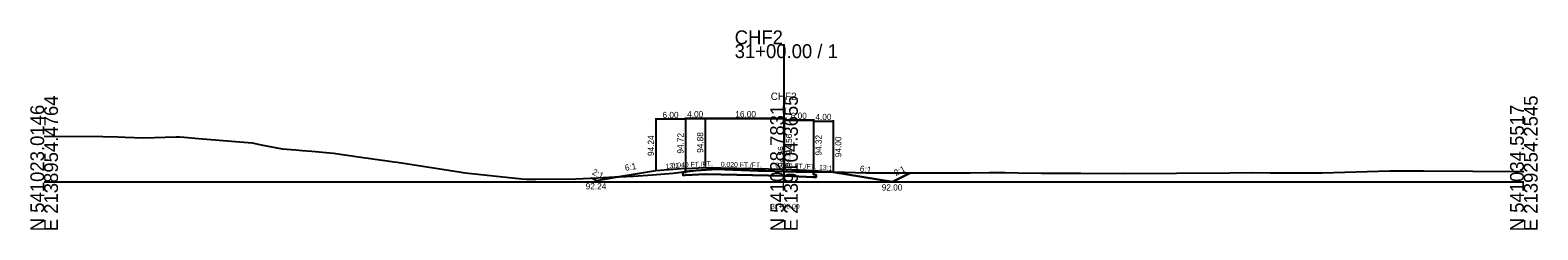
# Model space of a CAD drawing. Extents: x -12831 to 2303, y -10 to 39065.
# Drawn here: x 997.2 to 1302.8, y 1990.3 to 2030.7 of the extents above; entities that cross this region are included whole.
import ezdxf

# ---------------------------------------------------------------- set-up
doc = ezdxf.new("R2010")
doc.units = 0
for name, color, linetype in [('Level 5', 7, 'Continuous'), ('Level 53', 7, 'Continuous'), ('Level 54', 7, 'Continuous'), ('Level 55', 7, 'Continuous'), ('Level 7', 7, 'Continuous'), ('RD_GPK_XS_Cell', 7, 'Continuous'), ('RD_XS_EwShp', 7, 'Continuous'), ('RD_XS_ExGround', 7, 'Continuous'), ('RD_XS_Pave', 7, 'Continuous'), ('RD_XS_TX_Baseline', 7, 'Continuous'), ('RD_XS_TX_Ditch', 7, 'Continuous'), ('RD_XS_TX_Elev_EX', 7, 'Continuous'), ('RD_XS_TX_Elev_PR', 7, 'Continuous'), ('RD_XS_TX_Station', 7, 'Continuous')]:
    doc.layers.add(name, color=color, linetype=linetype)

msp = doc.modelspace()

# ---------------------------------------------------------------- linework, layer by layer
at = {"layer": 'Level 5'}
for p, q in [((1130, 2002.72), (1130, 2001.88)), ((1156, 2002.32), (1156, 2001.48)), ((1130, 2001.88), (1129.5, 2001.86)), ((1129.5, 2001.86), (1129.5, 2001.36)), ((1129.5, 2001.36), (1130, 2001.38)), ((1134, 2001.54), (1130, 2001.38)), ((1134, 2001.54), (1130, 2001.38)), ((1130, 2001.38), (1134, 2001.54)), ((1150, 2001.22), (1134, 2001.54)), ((1150, 2001.22), (1134, 2001.54)), ((1134, 2001.54), (1150, 2001.22)), ((1134, 2001.54), (1150, 2001.22)), ((1156, 2000.98), (1150, 2001.22)), ((1150, 2001.22), (1156, 2000.98)), ((1150, 2001.22), (1156, 2000.98)), ((1156, 2001.48), (1156.5, 2001.46)), ((1156.5, 2000.96), (1156, 2000.98)), ((1156.5, 2001.46), (1156.5, 2000.96))]:
    msp.add_line(p, q, dxfattribs=at)
at = {"layer": 'Level 54'}
for p, q in [((1124, 2012.87), (1124, 2002.44)), ((1130, 2012.67), (1124, 2012.67)), ((1130, 2013.03), (1130, 2002.92)), ((1130, 2013.03), (1130, 2002.92)), ((1130, 2013.03), (1130, 2002.92)), ((1130, 2012.87), (1130, 2002.92)), ((1130, 2012.83), (1134, 2012.83)), ((1130, 2012.83), (1134, 2012.83)), ((1134, 2012.83), (1130, 2012.83)), ((1134, 2013.03), (1134, 2003.08)), ((1134, 2013.03), (1134, 2003.08)), ((1134, 2013.03), (1134, 2003.08)), ((1134, 2013.03), (1134, 2003.08)), ((1134, 2013.03), (1134, 2003.08)), ((1134, 2013.03), (1134, 2003.08)), ((1134, 2013.03), (1134, 2003.08)), ((1134, 2012.83), (1150, 2012.83)), ((1134, 2012.83), (1150, 2012.83)), ((1150, 2012.83), (1134, 2012.83)), ((1150, 2012.83), (1134, 2012.83)), ((1150, 2013.03), (1150, 2002.76)), ((1150, 2013.03), (1150, 2002.76)), ((1150, 2013.03), (1150, 2002.76)), ((1150, 2013.03), (1150, 2002.76)), ((1150, 2012.71), (1150, 2002.76)), ((1150, 2012.71), (1150, 2002.76)), ((1150, 2012.71), (1150, 2002.76)), ((1150, 2012.51), (1156, 2012.51)), ((1156, 2012.51), (1150, 2012.51)), ((1156, 2012.51), (1150, 2012.51)), ((1156, 2012.71), (1156, 2002.52)), ((1156, 2012.71), (1156, 2002.52)), ((1156, 2012.71), (1156, 2002.52)), ((1156, 2012.47), (1156, 2002.52)), ((1156, 2012.27), (1160, 2012.27)), ((1160, 2012.47), (1160, 2002.2))]:
    msp.add_line(p, q, dxfattribs=at)
at = {"layer": 'Level 7'}
for p, q in [((1124, 2002.24), (1112, 2000.24)), ((1130, 2002.72), (1124, 2002.24)), ((1156, 2002.32), (1160, 2002)), ((1112, 2000.24), (1110.94, 2000.77)), ((1160, 2002), (1172, 2000)), ((1172, 2000), (1175.67, 2001.83))]:
    msp.add_line(p, q, dxfattribs=at)
at = {"layer": 'RD_GPK_XS_Cell'}
for p, q in [((1150, 2000), (1150, 2027.85)), ((1000, 2000), (1150, 2000)), ((1150, 2000), (1300, 2000))]:
    msp.add_line(p, q, dxfattribs=at)
at = {"layer": 'RD_XS_EwShp'}
for points in [[(1116.94, 2001.06), (1119.46, 2001.18), (1123.36, 2001.42), (1127.52, 2001.79), (1130, 2002.08), (1130, 2002.72), (1124, 2002.24)], [(1130, 2002.08), (1130, 2001.88), (1129.5, 2001.86), (1129.5, 2001.36), (1130, 2001.38), (1134, 2001.54), (1150, 2001.22), (1156, 2000.98), (1156.5, 2000.96), (1156.5, 2001.46), (1156, 2001.48), (1156, 2002.04), (1152.47, 2002.04), (1150, 2002.11), (1146.28, 2002.22), (1144.76, 2002.27), (1136.3, 2002.59), (1132.2, 2002.33)], [(1156, 2002.32), (1159.42, 2002.04), (1156, 2002.04)], [(1110.94, 2000.77), (1116.94, 2001.06), (1112, 2000.24)], [(1159.42, 2002.04), (1160.14, 2002.04), (1166.68, 2001.82), (1175.67, 2001.83), (1172, 2000), (1160, 2002)]]:
    msp.add_lwpolyline(points, close=True, dxfattribs=at)
at = {"layer": 'RD_XS_ExGround'}
for p, q in [((1000, 2009.28), (1011.87, 2009.17)), ((1011.87, 2009.17), (1014.96, 2009.14)), ((1014.96, 2009.14), (1016.44, 2009.06)), ((1016.44, 2009.06), (1020.16, 2008.93)), ((1020.16, 2008.93), (1026.77, 2009.11)), ((1026.77, 2009.11), (1027.47, 2009.13)), ((1027.47, 2009.13), (1028.41, 2009.06)), ((1028.41, 2009.06), (1031.26, 2008.81)), ((1031.26, 2008.81), (1042.14, 2007.87)), ((1042.14, 2007.87), (1043.97, 2007.5)), ((1043.97, 2007.5), (1048.27, 2006.67)), ((1048.27, 2006.67), (1051.02, 2006.47)), ((1051.02, 2006.47), (1052.29, 2006.34)), ((1052.29, 2006.34), (1054.3, 2006.21)), ((1054.3, 2006.21), (1058.64, 2005.8)), ((1058.64, 2005.8), (1063.75, 2005.05)), ((1063.75, 2005.05), (1070.04, 2004.18)), ((1070.04, 2004.18), (1070.89, 2004.07)), ((1070.89, 2004.07), (1071.58, 2003.96)), ((1071.58, 2003.96), (1079.8, 2002.68)), ((1079.8, 2002.68), (1084.53, 2001.95)), ((1127.52, 2001.79), (1132.2, 2002.33)), ((1132.2, 2002.33), (1136.3, 2002.59)), ((1136.3, 2002.59), (1144.76, 2002.27)), ((1144.76, 2002.27), (1146.28, 2002.22)), ((1146.28, 2002.22), (1150, 2002.11)), ((1259.1, 2001.85), (1272.81, 2002.26)), ((1272.81, 2002.26), (1273.54, 2002.26)), ((1273.54, 2002.26), (1274.11, 2002.26)), ((1274.11, 2002.26), (1279.65, 2002.24)), ((1279.65, 2002.24), (1299.67, 2002.11)), ((1084.53, 2001.95), (1085.39, 2001.83)), ((1085.39, 2001.83), (1096.85, 2000.6)), ((1096.85, 2000.6), (1097.77, 2000.53)), ((1097.77, 2000.53), (1099.68, 2000.53)), ((1099.68, 2000.53), (1107.79, 2000.61)), ((1107.79, 2000.61), (1119.46, 2001.18)), ((1119.46, 2001.18), (1123.36, 2001.42)), ((1123.36, 2001.42), (1127.52, 2001.79)), ((1150, 2002.11), (1152.47, 2002.04)), ((1152.47, 2002.04), (1160.14, 2002.04)), ((1160.14, 2002.04), (1166.68, 2001.82)), ((1166.68, 2001.82), (1187.75, 2001.84)), ((1187.75, 2001.84), (1191.67, 2001.9)), ((1191.67, 2001.9), (1194.87, 2001.91)), ((1194.87, 2001.91), (1197.41, 2001.85)), ((1197.41, 2001.85), (1202.2, 2001.77)), ((1202.2, 2001.77), (1208.81, 2001.77)), ((1208.81, 2001.77), (1209.82, 2001.78)), ((1209.82, 2001.78), (1210.19, 2001.78)), ((1210.19, 2001.78), (1218.8, 2001.72)), ((1218.8, 2001.72), (1240.34, 2001.81)), ((1240.34, 2001.81), (1245.02, 2001.88)), ((1245.02, 2001.88), (1248.54, 2001.81)), ((1248.54, 2001.81), (1256.68, 2001.8)), ((1256.68, 2001.8), (1259.1, 2001.85)), ((1299.67, 2002.11), (1300, 2002.11))]:
    msp.add_line(p, q, dxfattribs=at)
at = {"layer": 'RD_XS_Pave'}
for p, q in [((1130, 2002.72), (1134, 2002.88)), ((1134, 2002.88), (1150, 2002.56)), ((1150, 2002.56), (1156, 2002.32))]:
    msp.add_line(p, q, dxfattribs=at)

# ---------------------------------------------------------------- texts
at = {"layer": 'Level 53'}
for s, rotation, p in [('94.24', 90, (1123.63, 2005.24)), ('94.72', 90, (1129.63, 2005.72)), ('94.88', 90, (1133.63, 2005.88)), ('94.88', 90, (1133.63, 2005.88)), ('94.56', 90, (1151.63, 2005.56)), ('94.56', 90, (1151.63, 2005.56)), ('94.32', 90, (1157.63, 2005.32)), ('94.00', 90, (1161.63, 2005)), ('6:1', 9.4623, (1117.84, 2002.22)), ('6:1', 350.5377, (1165.3, 2002.13))]:
    msp.add_text(s, height=1.25, rotation=rotation, dxfattribs=at).set_placement(p)
msp.add_text('92.00', height=1.25, dxfattribs=at).set_placement((1169.81, 1998.25))
at = {"layer": 'Level 54'}
for s, p in [('6.00', (1125.37, 2012.92)), ('4.00', (1130.37, 2013.08)), ('4.00', (1130.37, 2013.08)), ('4.00', (1130.37, 2013.08)), ('16.00', (1140.13, 2013.08)), ('16.00', (1140.13, 2013.08)), ('16.00', (1140.13, 2013.08)), ('16.00', (1140.13, 2013.08)), ('6.00', (1151.37, 2012.76)), ('6.00', (1151.37, 2012.76)), ('6.00', (1151.37, 2012.76)), ('4.00', (1156.37, 2012.52))]:
    msp.add_text(s, height=1.25, dxfattribs=at).set_placement(p)
at = {"layer": 'Level 55'}
for s, height, rotation, p in [('2:1', 1.25, 333.4349, (1110.96, 2001.59)), ('13:1', 1, 4.5739, (1126.03, 2002.65)), ('0.040 FT./FT.', 1, 2.2906, (1127.22, 2002.85)), ('0.040 FT./FT.', 1, 2.2906, (1127.22, 2002.85)), ('0.040 FT./FT.', 1, 2.2906, (1127.22, 2002.85)), ('0.020 FT./FT.', 1, 358.8542, (1137.18, 2003.06)), ('0.020 FT./FT.', 1, 358.8542, (1137.18, 2003.06)), ('0.020 FT./FT.', 1, 358.8542, (1137.18, 2003.06)), ('0.020 FT./FT.', 1, 358.8542, (1137.18, 2003.06)), ('0.040 FT./FT.', 1, 357.7094, (1148.24, 2002.88)), ('0.040 FT./FT.', 1, 357.7094, (1148.24, 2002.88)), ('0.040 FT./FT.', 1, 357.7094, (1148.24, 2002.88)), ('13:1', 1, 355.4261, (1157.07, 2002.48)), ('2:1', 1.25, 26.5651, (1172.66, 2001.16))]:
    msp.add_text(s, height=height, rotation=rotation, dxfattribs=at).set_placement(p)
at = {"layer": 'RD_GPK_XS_Cell'}
for s, p in [('CHF2', (1140, 2027.85)), ('31+00.00 / 1', (1140, 2025.05))]:
    msp.add_text(s, height=2.8, dxfattribs=at).set_placement(p)
for s, p in [('N 541023.0146', (1000, 1990)), ('E 2138954.4764', (1002.8, 1990)), ('N 541028.7831', (1150, 1990)), ('E 2139104.3655', (1152.8, 1990)), ('N 541034.5517', (1300, 1990)), ('E 2139254.2545', (1302.8, 1990))]:
    msp.add_text(s, height=2.8, rotation=90, dxfattribs=at).set_placement(p)
at = {"layer": 'RD_XS_TX_Baseline'}
msp.add_text('CHF2', height=1.5, dxfattribs=at).set_placement((1147.31, 2016.56))
at = {"layer": 'RD_XS_TX_Ditch'}
msp.add_text('92.24', height=1.25, dxfattribs=at).set_placement((1109.79, 1998.49))
at = {"layer": 'RD_XS_TX_Elev_EX'}
msp.add_text('94.11', height=1, rotation=90, dxfattribs=at).set_placement((1151.25, 2003.11))
at = {"layer": 'RD_XS_TX_Elev_PR'}
msp.add_text(' 94.56', height=1.25, rotation=90, dxfattribs=at).set_placement((1150, 2002.56))
at = {"layer": 'RD_XS_TX_Station'}
msp.add_text('31+00.00', height=1, dxfattribs=at).set_placement((1147.37, 1994.56))

doc.saveas('drawing.dxf')
